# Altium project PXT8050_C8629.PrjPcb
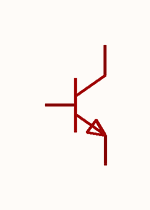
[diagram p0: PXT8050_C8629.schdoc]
1 sheet, 1 parts. Net scope: global (net labels, ports and power ports of the same name join across sheets).

## Sheet PXT8050_C8629.schdoc
size 127 x 101 mm

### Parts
Q?  pxt8050(range:200-350)  [SOT-89-3_L4.5-W2.5-P1.50-LS4.2-BR]  (value not drawn)

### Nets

Not connected (* = marked no-connect by the designer): Q? 1(B) 2(C) 3(E)

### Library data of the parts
Q? = pxt8050(range:200-350): 晶体管类型:NPN;集电极电流(Ic):1.5A;集射极击穿电压(Vceo):25V;耗散功率(Pd):500mW;直流电流增益(hFE):200;; Manufacturer: CJ(江苏长电/长晶); Symbol: PXT8050_C8629; AddInBom: yes; ModelId: 6db690b7897d4d18a30d90c1b89525ee; ModelName: SOT-89-3_L4.3-W2.5-H1.6-LS4.1-P1.50; ModelTransform: 161.417,169.291,0,180,0,0,-18.661,0,0; type: NPN; Current - Collector(Ic): 1.5A; Collector - Emitter Voltage VCEO: 25V; Pd - Power Dissipation: 500mW; DC Current Gain: 200; Transition frequency(fT): 100MHz; Current - Collector Cutoff: 100nA; Vce Saturation(VCE(sat)): 500mV; Emitter-Base Voltage(Vebo): 5V; Number: 1个NPN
